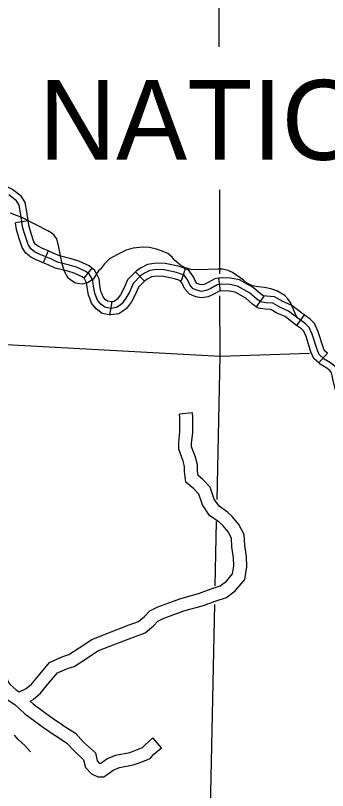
# Model space of a CAD drawing. Extents: x 1373862 to 1376999, y 1168398 to 1170455.
# Drawn here: x 1375936.3 to 1376008.5, y 1169215.8 to 1169395.2 of the extents above; entities that cross this region are included whole.
import ezdxf

# ---------------------------------------------------------------- set-up
doc = ezdxf.new("R2010")
doc.units = 0
for name, color, linetype in [('Level 32', 7, 'Continuous'), ('Level 45', 7, 'Continuous'), ('Level 46', 7, 'Continuous'), ('Level 5', 7, 'Continuous'), ('Level 8', 7, 'Continuous')]:
    doc.layers.add(name, color=color, linetype=linetype)

msp = doc.modelspace()

# ---------------------------------------------------------------- linework, layer by layer
at = {"layer": 'Level 32'}
for p, q in [((1375939.22, 1169347.67), (1375936.25, 1169347.22)), ((1375943.79, 1169340.72), (1375942.63, 1169337.95)), ((1375953.94, 1169336.73), (1375952.07, 1169334.39)), ((1375975.57, 1169336.58), (1375974.62, 1169333.74)), ((1375964.04, 1169335.83), (1375966.16, 1169333.71)), ((1375983.29, 1169334.37), (1375983.69, 1169331.4)), ((1375993.77, 1169330.2), (1375992.01, 1169327.78)), ((1375958.58, 1169328.88), (1375958.03, 1169325.93)), ((1376003.12, 1169325.88), (1376001.35, 1169323.46)), ((1376008.51, 1169317), (1376006.49, 1169314.79))]:
    msp.add_line(p, q, dxfattribs=at)
for points in [[(1375939.22, 1169347.67), (1375938.91, 1169349.73), (1375938.5, 1169351.87), (1375937.61, 1169353.29), (1375935.55, 1169354.93), (1375933.31, 1169356.1), (1375932.22, 1169356.45)], [(1376001.63, 1169325.11), (1375999.48, 1169326.79), (1375997.48, 1169327.66), (1375995.82, 1169328.62), (1375994.25, 1169328.71), (1375993.03, 1169328.88), (1375992.08, 1169329.58), (1375990.42, 1169330.98), (1375987.63, 1169332.55), (1375985.89, 1169332.9), (1375984.23, 1169332.98), (1375982.93, 1169332.81), (1375981.53, 1169332.02), (1375980.4, 1169331.5), (1375979.35, 1169331.33), (1375978.48, 1169331.5), (1375977.43, 1169331.94), (1375976.65, 1169332.81), (1375976.13, 1169333.94), (1375975.34, 1169335.08), (1375974.82, 1169335.25), (1375973.51, 1169335.69), (1375970.72, 1169336.3), (1375968.89, 1169336.39), (1375967.33, 1169336.13), (1375966.11, 1169335.51), (1375965.23, 1169334.9), (1375963.49, 1169333.16), (1375962.71, 1169331.33), (1375961.83, 1169329.76), (1375960.88, 1169328.45), (1375960.27, 1169328.01), (1375959.66, 1169327.57), (1375958.35, 1169327.4), (1375956.95, 1169327.66), (1375956, 1169328.36), (1375955.21, 1169329.32), (1375954.95, 1169330.1), (1375954.6, 1169330.89), (1375954.34, 1169332.55), (1375954.17, 1169333.77), (1375953.82, 1169334.47), (1375953.38, 1169335.25), (1375952.51, 1169335.95), (1375950.42, 1169336.91), (1375948.76, 1169337.43), (1375945.97, 1169338.13), (1375944.4, 1169338.83), (1375941.7, 1169339.97), (1375940.66, 1169340.49), (1375939.79, 1169341.19), (1375939.18, 1169342.15), (1375938.48, 1169344.24), (1375937.96, 1169345.99), (1375937.43, 1169349.48), (1375937.08, 1169351.31), (1375936.47, 1169352.27), (1375934.73, 1169353.67)], [(1375942.63, 1169337.95), (1375941.08, 1169338.6), (1375939.84, 1169339.22), (1375938.65, 1169340.17), (1375937.81, 1169341.5), (1375937.05, 1169343.79), (1375936.49, 1169345.66), (1375936.25, 1169347.22)], [(1375943.79, 1169340.72), (1375942.33, 1169341.33), (1375941.47, 1169341.76), (1375940.92, 1169342.2), (1375940.54, 1169342.8), (1375939.91, 1169344.69), (1375939.42, 1169346.32), (1375939.22, 1169347.67)], [(1375953.94, 1169336.73), (1375953.3, 1169337.24), (1375950.96, 1169338.31), (1375949.17, 1169338.88), (1375946.46, 1169339.56), (1375945, 1169340.21), (1375943.79, 1169340.72)], [(1375952.07, 1169334.39), (1375951.72, 1169334.67), (1375949.88, 1169335.51), (1375948.35, 1169335.99), (1375945.48, 1169336.71), (1375943.81, 1169337.45), (1375942.63, 1169337.95)], [(1375958.58, 1169328.88), (1375957.56, 1169329.07), (1375957.03, 1169329.46), (1375956.55, 1169330.05), (1375956.35, 1169330.65), (1375956.05, 1169331.32), (1375955.82, 1169332.77), (1375955.62, 1169334.22), (1375955.14, 1169335.17), (1375954.55, 1169336.24), (1375953.94, 1169336.73)], [(1375975.57, 1169336.58), (1375975.3, 1169336.68), (1375973.91, 1169337.14), (1375970.92, 1169337.79), (1375968.81, 1169337.89), (1375966.86, 1169337.57), (1375965.33, 1169336.81), (1375964.27, 1169336.06), (1375964.04, 1169335.83)], [(1375983.29, 1169334.37), (1375982.44, 1169334.26), (1375980.85, 1169333.36), (1375979.95, 1169332.95), (1375979.38, 1169332.85), (1375978.92, 1169332.94), (1375978.32, 1169333.19), (1375977.92, 1169333.64), (1375977.44, 1169334.69), (1375976.29, 1169336.34), (1375975.57, 1169336.58)], [(1375964.04, 1169335.83), (1375962.23, 1169334.01), (1375961.36, 1169331.99), (1375960.57, 1169330.57), (1375959.81, 1169329.53), (1375959.39, 1169329.23), (1375959.09, 1169329.01), (1375958.39, 1169328.92), (1375958.58, 1169328.88)], [(1375974.62, 1169333.74), (1375974.35, 1169333.83), (1375973.11, 1169334.24), (1375970.53, 1169334.81), (1375968.98, 1169334.88), (1375967.79, 1169334.68), (1375966.88, 1169334.22), (1375966.2, 1169333.75), (1375966.16, 1169333.71)], [(1375958.03, 1169325.93), (1375956.34, 1169326.25), (1375954.96, 1169327.26), (1375953.88, 1169328.58), (1375953.55, 1169329.56), (1375953.15, 1169330.46), (1375952.86, 1169332.33), (1375952.71, 1169333.32), (1375952.49, 1169333.77), (1375952.21, 1169334.27), (1375952.07, 1169334.39)], [(1375966.16, 1169333.71), (1375964.76, 1169332.3), (1375964.06, 1169330.67), (1375963.1, 1169328.94), (1375961.94, 1169327.37), (1375961.14, 1169326.79), (1375960.22, 1169326.14), (1375958.31, 1169325.88), (1375958.03, 1169325.93)], [(1375983.69, 1169331.4), (1375983.41, 1169331.36), (1375982.21, 1169330.69), (1375980.84, 1169330.05), (1375979.33, 1169329.8), (1375978.04, 1169330.06), (1375976.55, 1169330.68), (1375975.38, 1169331.98), (1375974.82, 1169333.2), (1375974.39, 1169333.81), (1375974.62, 1169333.74)], [(1375993.77, 1169330.2), (1375993, 1169330.76), (1375991.28, 1169332.21), (1375988.16, 1169333.97), (1375986.08, 1169334.39), (1375984.17, 1169334.49), (1375983.29, 1169334.37)], [(1375992.01, 1169327.78), (1375991.15, 1169328.4), (1375989.56, 1169329.74), (1375987.1, 1169331.12), (1375985.7, 1169331.4), (1375984.29, 1169331.48), (1375983.69, 1169331.4)], [(1376003.12, 1169325.88), (1376002.54, 1169326.31), (1376000.26, 1169328.09), (1375998.16, 1169329), (1375996.27, 1169330.1), (1375994.4, 1169330.2), (1375993.62, 1169330.31), (1375993.77, 1169330.2)], [(1376001.35, 1169323.46), (1376000.73, 1169323.91), (1375998.71, 1169325.49), (1375996.8, 1169326.32), (1375995.38, 1169327.14), (1375994.11, 1169327.21), (1375992.45, 1169327.45), (1375992.01, 1169327.78)], [(1376008.51, 1169317), (1376007.85, 1169317.61), (1376007.48, 1169318.41), (1376006.38, 1169321.99), (1376005.49, 1169323.9), (1376004.39, 1169324.95), (1376003.12, 1169325.88)], [(1376022.43, 1169296.56), (1376020.07, 1169296.6), (1376018.51, 1169297.15), (1376017.19, 1169298.27), (1376016.58, 1169299.2), (1376014.8, 1169303.92), (1376013.69, 1169305.49), (1376012.99, 1169306.21), (1376012.41, 1169307.16), (1376011.74, 1169309.18), (1376011.27, 1169311.01), (1376011.08, 1169312.25), (1376010.78, 1169313.12), (1376010.29, 1169313.98), (1376009.23, 1169314.79), (1376007.73, 1169315.68), (1376006.61, 1169316.71), (1376006.08, 1169317.87), (1376004.98, 1169321.44), (1376004.25, 1169323.01), (1376003.43, 1169323.79), (1376001.63, 1169325.11)], [(1376006.49, 1169314.79), (1376005.38, 1169315.81), (1376004.68, 1169317.34), (1376003.58, 1169320.9), (1376003.01, 1169322.12), (1376002.46, 1169322.64), (1376001.35, 1169323.46)], [(1376010.98, 1169306.7), (1376010.3, 1169308.76), (1376009.8, 1169310.71), (1376009.62, 1169311.89), (1376009.41, 1169312.5), (1376009.14, 1169312.97), (1376008.39, 1169313.54), (1376006.83, 1169314.47), (1376006.49, 1169314.79)]]:
    msp.add_lwpolyline(points, dxfattribs=at)
at = {"layer": 'Level 45'}
for points in [[(1376009.23, 1169314.79), (1376007.73, 1169315.68), (1376006.61, 1169316.71), (1376006.08, 1169317.87), (1376004.98, 1169321.44), (1376004.25, 1169323.01), (1376003.43, 1169323.79), (1376001.63, 1169325.11), (1376001.25, 1169325.65), (1375999.99, 1169328.58), (1375999.31, 1169329.59), (1375998.6, 1169330.4), (1375996.76, 1169331.43), (1375995.36, 1169331.94), (1375993.94, 1169332.25), (1375992.45, 1169332.37), (1375991.17, 1169332.62), (1375989.73, 1169333.33), (1375989.06, 1169333.92), (1375986.5, 1169335.69), (1375985.52, 1169336.14), (1375984.2, 1169336.47), (1375983.14, 1169336.51), (1375978.65, 1169336.34), (1375976.95, 1169336.38), (1375975.55, 1169336.79), (1375974.47, 1169337.42), (1375973.17, 1169338.45), (1375972.54, 1169339.23), (1375971.53, 1169340.07), (1375970.24, 1169340.65), (1375968.93, 1169341.08), (1375967.31, 1169341.47), (1375965.77, 1169341.56), (1375963.52, 1169341.33), (1375961.9, 1169340.88), (1375959.69, 1169339.79), (1375958.04, 1169338.84), (1375956.83, 1169337.71), (1375955.96, 1169336.51), (1375955.46, 1169336.07), (1375954.24, 1169334.13), (1375952.9, 1169333.3), (1375951.73, 1169332.97), (1375950.11, 1169333.2), (1375948.45, 1169334.37), (1375947.6, 1169335.96), (1375947.09, 1169337.68), (1375946.31, 1169341.57), (1375945.82, 1169343.52), (1375945.14, 1169344.4), (1375944.53, 1169344.91), (1375943.75, 1169345.37), (1375937.91, 1169348.39), (1375935.09, 1169349.43)], [(1375939.74, 1169224.8), (1375938.43, 1169226.19), (1375936.89, 1169227.62), (1375936.04, 1169228.63)]]:
    msp.add_lwpolyline(points, dxfattribs=at)
at = {"layer": 'Level 46'}
for points in [[(1375937.13, 1169238.61), (1375938.71, 1169239.43), (1375939.95, 1169240.45), (1375941.86, 1169242.77), (1375944.16, 1169245.46), (1375947.24, 1169246.86), (1375948.6, 1169247.26), (1375951.01, 1169248.86), (1375953.91, 1169250.77), (1375958.39, 1169252.56), (1375962.57, 1169254.13), (1375964.75, 1169254.91), (1375966.12, 1169256.06), (1375967.36, 1169257.41), (1375969.24, 1169258.35), (1375974.31, 1169260.21), (1375978.9, 1169261.52), (1375981.55, 1169262.46), (1375983.67, 1169263.16), (1375985.15, 1169264.29), (1375986.52, 1169265.94), (1375986.85, 1169267.81), (1375986.78, 1169269.63), (1375986.34, 1169272.23), (1375986.27, 1169274.23), (1375985.47, 1169275.69), (1375984.33, 1169277.06), (1375983.43, 1169277.88), (1375981.21, 1169279.46), (1375979.56, 1169281.94), (1375978.73, 1169284.41), (1375977.55, 1169285.66), (1375975.68, 1169287.21), (1375975.43, 1169289.63), (1375975.43, 1169290.79), (1375975.08, 1169292.01), (1375974.05, 1169294.81), (1375974.05, 1169296.37), (1375974.31, 1169298.79), (1375974.31, 1169300.71), (1375974.31, 1169302.1), (1375974.23, 1169302.9)], [(1375939.62, 1169236.52), (1375940.38, 1169236.91), (1375942.08, 1169238.32), (1375944.16, 1169240.85), (1375946.01, 1169243.01), (1375948.29, 1169244.04), (1375949.88, 1169244.51), (1375952.66, 1169246.36), (1375955.3, 1169248.1), (1375959.47, 1169249.77), (1375963.6, 1169251.31), (1375966.27, 1169252.27), (1375968.19, 1169253.89), (1375969.19, 1169254.97), (1375970.43, 1169255.59), (1375975.23, 1169257.36), (1375979.81, 1169258.66), (1375982.53, 1169259.62), (1375985.09, 1169260.47), (1375987.24, 1169262.11), (1375989.33, 1169264.63), (1375989.86, 1169267.61), (1375989.77, 1169269.94), (1375989.33, 1169272.54), (1375989.24, 1169275.05), (1375987.96, 1169277.39), (1375986.5, 1169279.14), (1375985.32, 1169280.22), (1375983.39, 1169281.59), (1375982.27, 1169283.27), (1375981.37, 1169285.99), (1375979.6, 1169287.86), (1375978.54, 1169288.74), (1375978.43, 1169289.78), (1375978.43, 1169291.22), (1375977.93, 1169292.95), (1375977.05, 1169295.34), (1375977.05, 1169296.21), (1375977.31, 1169298.63), (1375977.31, 1169300.71), (1375977.31, 1169302.25), (1375977.21, 1169303.19), (1375974.23, 1169302.9)], [(1375929.57, 1169246.54), (1375932.08, 1169245.12), (1375933.27, 1169243.51), (1375934.15, 1169242.03), (1375934.62, 1169240.77), (1375934.99, 1169240.36), (1375936.4, 1169239.1), (1375937.13, 1169238.61)], [(1375928.47, 1169243.72), (1375930.04, 1169242.83), (1375930.76, 1169241.85), (1375931.44, 1169240.72), (1375932, 1169239.21), (1375932.85, 1169238.24), (1375934.56, 1169236.72), (1375936.1, 1169235.69), (1375938.41, 1169233.55), (1375942.75, 1169230.36), (1375945.45, 1169228.53)], [(1375939.62, 1169236.52), (1375940.33, 1169235.87), (1375944.48, 1169232.82), (1375947.14, 1169231.01)], [(1375947.1, 1169231.04), (1375950.13, 1169229.11), (1375952.04, 1169227.02), (1375954.75, 1169224.5), (1375955.19, 1169222.65), (1375955.67, 1169222.17), (1375955.87, 1169222.07), (1375956.53, 1169222.52), (1375957.42, 1169223.12), (1375959.43, 1169224.02), (1375962.7, 1169224.64), (1375964.29, 1169225.2), (1375965.66, 1169225.75), (1375966.19, 1169226.34), (1375968.08, 1169227.97)], [(1375945.49, 1169228.51), (1375948.18, 1169226.79), (1375949.9, 1169224.9), (1375952.04, 1169222.92), (1375952.46, 1169221.13), (1375953.89, 1169219.7), (1375955.29, 1169219), (1375956.72, 1169219), (1375958.22, 1169220.04), (1375958.88, 1169220.49), (1375960.34, 1169221.14), (1375963.48, 1169221.74), (1375965.34, 1169222.39), (1375967.43, 1169223.23), (1375968.29, 1169224.2), (1375970.03, 1169225.69), (1375968.08, 1169227.97)]]:
    msp.add_lwpolyline(points, dxfattribs=at)
at = {"layer": 'Level 5'}
for points in [[(1375983.45, 1169387.9), (1375983.36, 1169425.83)], [(1375983.59, 1169335.42), (1375983.54, 1169354.83)], [(1375983.64, 1169316.28), (1375983.6, 1169330.33)], [(1376004.33, 1169316.92), (1375983.64, 1169316.28), (1375877.48, 1169322.08), (1375864.27, 1169322.28)], [(1375982.93, 1169283.2), (1375983.64, 1169316.28)], [(1375982.49, 1169263.2), (1375982.82, 1169278.06)], [(1375981.38, 1169211.52), (1375981.38, 1169211.61), (1375982.4, 1169258.88)]]:
    msp.add_lwpolyline(points, dxfattribs=at)

# ---------------------------------------------------------------- texts
at = {"layer": 'Level 8'}
msp.add_text('NATIONAL', height=18.48, dxfattribs=at).set_placement((1375941.7, 1169361.78))

doc.saveas('drawing.dxf')
